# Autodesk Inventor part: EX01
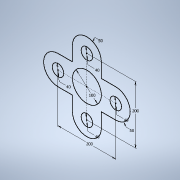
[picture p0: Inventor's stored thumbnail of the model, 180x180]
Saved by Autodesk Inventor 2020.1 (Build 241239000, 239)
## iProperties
Created: 2019-09
Part Number: EX01
Material: Generic
Document SubType Name: Modeling
Designer: Synergysoft Dell02
Density: 1 g/cm^3
Appearance: Default
Author: Synergysoft Dell02
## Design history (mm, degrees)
sketch "Sketch1"
  geometry: L1 (-100, 0)-(100, 0); L2 (0, -100)-(0, 100); L3 (-50, 100)-(-50, 50); L4 (100, 50)-(50, 50); L5 (-50, 50)-(-100, 50); L6 (50, -100)-(50, -50); L7 (50, 50)-(50, 100); L8 (-50, -50)-(-50, -100); L9 (-100, -50)-(-50, -50); L10 (50, -50)-(100, -50); C1 r 20 at (0, 100); C2 r 20 at (100, 0); C3 r 20 at (0, -100); C4 r 20 at (-100, 0); C5 r 50 at (0, 0); A1 r 50 centre (-100, 0) between (-100, 50) and (-100, -50); A2 r 50 centre (100, 0) between (100, -50) and (100, 50); A3 r 50 centre (0, -100) between (-50, -100) and (50, -100); A4 r 50 centre (0, 100) between (50, 100) and (-50, 100); 3 further points
  constraints: 24 end point, 16 tangent, 9 centre point, 8 parallel, 8 point on circle, 4 coincident, 3 concentric, 2 midpoint, 1 horizontal, 1 vertical
  dimensions: "d0" = 200 distance of L1.start L1.end; "d1" = 50 radius of A2; "d2" = 200 distance of L2.start L2.end; "d3" = 50 radius of A4; "d10" = 40 diameter of C1; "d11" = 40 diameter of C2; "d12" = 40 diameter of C3; "d13" = 40 diameter of C4; "d14" = 100 diameter of C5
